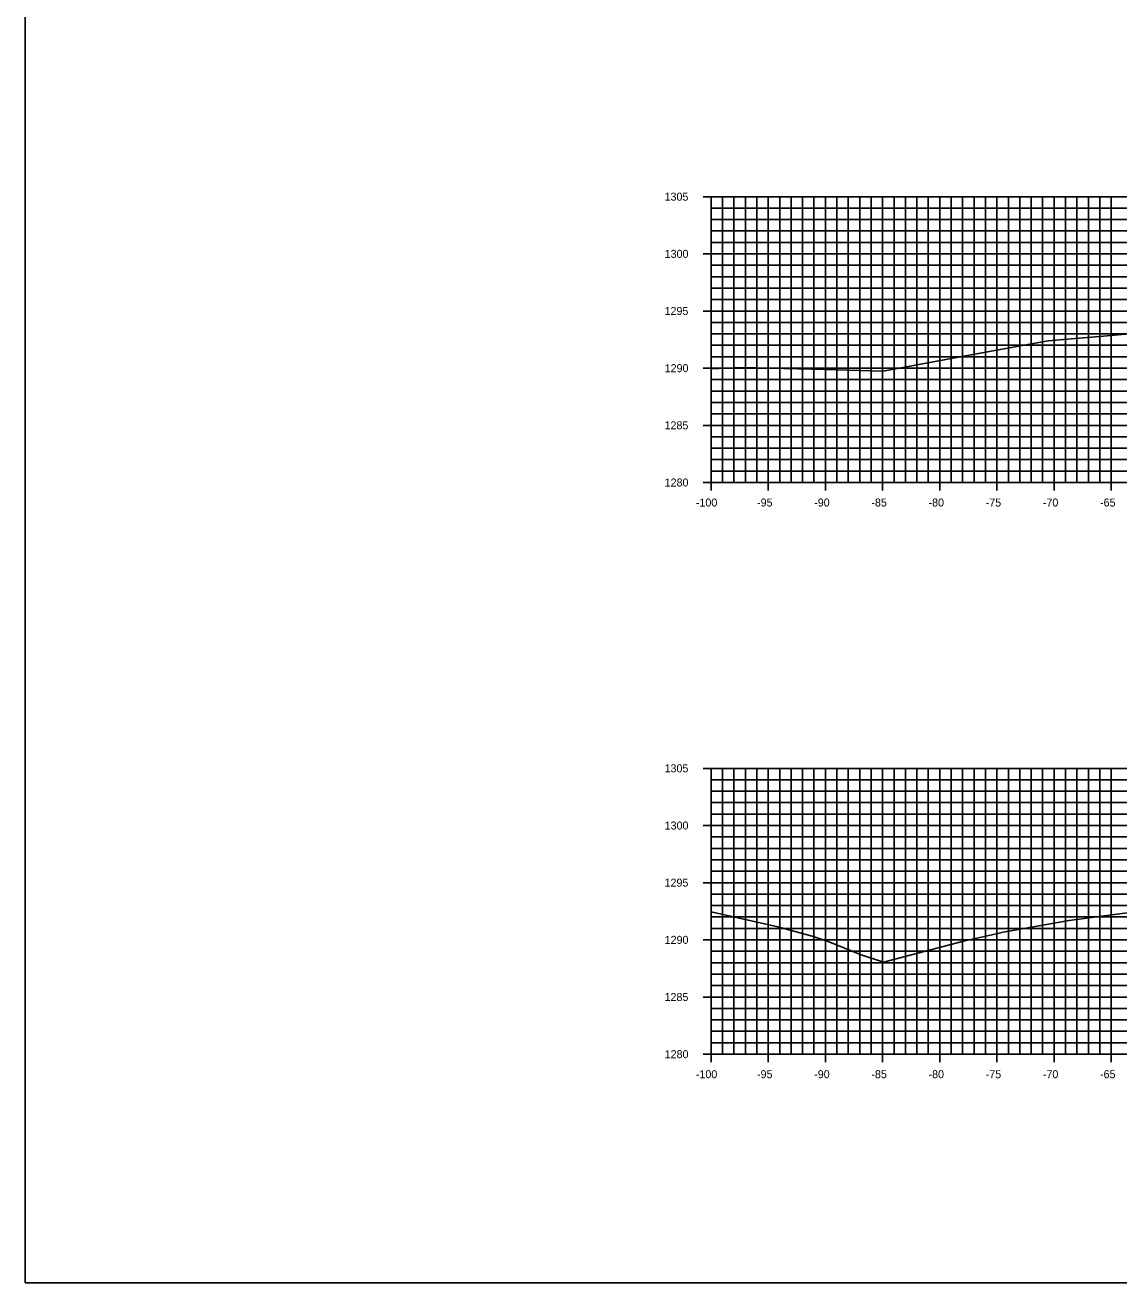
# Model space of a CAD drawing. Extents: x 674939 to 678919, y 750652 to 765176.
# Drawn here: x 678578.5 to 678674.2, y 757822.6 to 757932.6 of the extents above; entities that cross this region are included whole.
import ezdxf

# ---------------------------------------------------------------- set-up
doc = ezdxf.new("R2010")
doc.units = 0
for name, color, linetype in [('Level 10', 7, 'Continuous'), ('Level 20', 7, 'Continuous'), ('Level 4', 7, 'Continuous'), ('Level 8', 7, 'Continuous'), ('Level 9', 7, 'Continuous')]:
    doc.layers.add(name, color=color, linetype=linetype)

msp = doc.modelspace()

# ---------------------------------------------------------------- linework, layer by layer
at = {"layer": 'Level 10'}
for points in [[(678638.53, 757902.5), (678641.26, 757902.6), (678648.54, 757902.43), (678653.57, 757902.28), (678660.77, 757903.63), (678668.02, 757904.93), (678670.37, 757905.14), (678672.84, 757905.36), (678674.77, 757905.53)], [(678638.53, 757855), (678644.38, 757853.68), (678647.36, 757852.86), (678648.76, 757852.4), (678651.66, 757851.25), (678653.6, 757850.59), (678660.72, 757852.47), (678663.62, 757853.1), (678664.09, 757853.21), (678669.84, 757854.24), (678672.91, 757854.66), (678674.95, 757854.91)]]:
    msp.add_lwpolyline(points, dxfattribs=at)
at = {"layer": 'Level 20'}
for p, q in [((678638.53, 757917.55), (678838.53, 757917.55)), ((678638.53, 757892.55), (678638.53, 757917.55)), ((678638.53, 757916.55), (678838.53, 757916.55)), ((678639.53, 757892.55), (678639.53, 757917.55)), ((678640.53, 757892.55), (678640.53, 757917.55)), ((678641.53, 757892.55), (678641.53, 757917.55)), ((678642.53, 757892.55), (678642.53, 757917.55)), ((678643.53, 757892.55), (678643.53, 757917.55)), ((678644.53, 757892.55), (678644.53, 757917.55)), ((678645.53, 757892.55), (678645.53, 757917.55)), ((678646.53, 757892.55), (678646.53, 757917.55)), ((678647.53, 757892.55), (678647.53, 757917.55)), ((678648.53, 757892.55), (678648.53, 757917.55)), ((678649.53, 757892.55), (678649.53, 757917.55)), ((678650.53, 757892.55), (678650.53, 757917.55)), ((678651.53, 757892.55), (678651.53, 757917.55)), ((678652.53, 757892.55), (678652.53, 757917.55)), ((678653.53, 757892.55), (678653.53, 757917.55)), ((678654.53, 757892.55), (678654.53, 757917.55)), ((678655.53, 757892.55), (678655.53, 757917.55)), ((678656.53, 757892.55), (678656.53, 757917.55)), ((678657.53, 757892.55), (678657.53, 757917.55)), ((678658.53, 757892.55), (678658.53, 757917.55)), ((678659.53, 757892.55), (678659.53, 757917.55)), ((678660.53, 757892.55), (678660.53, 757917.55)), ((678661.53, 757892.55), (678661.53, 757917.55)), ((678662.53, 757892.55), (678662.53, 757917.55)), ((678663.53, 757892.55), (678663.53, 757917.55)), ((678664.53, 757892.55), (678664.53, 757917.55)), ((678665.53, 757892.55), (678665.53, 757917.55)), ((678666.53, 757892.55), (678666.53, 757917.55)), ((678667.53, 757892.55), (678667.53, 757917.55)), ((678668.53, 757892.55), (678668.53, 757917.55)), ((678669.53, 757892.55), (678669.53, 757917.55)), ((678670.53, 757892.55), (678670.53, 757917.55)), ((678671.53, 757892.55), (678671.53, 757917.55)), ((678672.53, 757892.55), (678672.53, 757917.55)), ((678673.53, 757892.55), (678673.53, 757917.55)), ((678638.53, 757915.55), (678838.53, 757915.55)), ((678638.53, 757914.55), (678838.53, 757914.55)), ((678638.53, 757913.55), (678838.53, 757913.55)), ((678638.53, 757912.55), (678838.53, 757912.55)), ((678638.53, 757911.55), (678838.53, 757911.55)), ((678638.53, 757910.55), (678838.53, 757910.55)), ((678638.53, 757909.55), (678838.53, 757909.55)), ((678638.53, 757908.55), (678838.53, 757908.55)), ((678638.53, 757907.55), (678838.53, 757907.55)), ((678638.53, 757906.55), (678838.53, 757906.55)), ((678638.53, 757905.55), (678838.53, 757905.55)), ((678638.53, 757904.55), (678838.53, 757904.55)), ((678638.53, 757903.55), (678838.53, 757903.55)), ((678638.53, 757902.55), (678838.53, 757902.55)), ((678638.53, 757901.55), (678838.53, 757901.55)), ((678638.53, 757900.55), (678838.53, 757900.55)), ((678638.53, 757899.55), (678838.53, 757899.55)), ((678638.53, 757898.55), (678838.53, 757898.55)), ((678638.53, 757897.55), (678838.53, 757897.55)), ((678638.53, 757896.55), (678838.53, 757896.55)), ((678638.53, 757895.55), (678838.53, 757895.55)), ((678638.53, 757894.55), (678838.53, 757894.55)), ((678638.53, 757893.55), (678838.53, 757893.55)), ((678638.53, 757892.55), (678838.53, 757892.55)), ((678638.53, 757867.55), (678838.53, 757867.55)), ((678638.53, 757842.55), (678638.53, 757867.55)), ((678639.53, 757842.55), (678639.53, 757867.55)), ((678640.53, 757842.55), (678640.53, 757867.55)), ((678641.53, 757842.55), (678641.53, 757867.55)), ((678642.53, 757842.55), (678642.53, 757867.55)), ((678643.53, 757842.55), (678643.53, 757867.55)), ((678644.53, 757842.55), (678644.53, 757867.55)), ((678645.53, 757842.55), (678645.53, 757867.55)), ((678646.53, 757842.55), (678646.53, 757867.55)), ((678647.53, 757842.55), (678647.53, 757867.55)), ((678648.53, 757842.55), (678648.53, 757867.55)), ((678649.53, 757842.55), (678649.53, 757867.55)), ((678650.53, 757842.55), (678650.53, 757867.55)), ((678651.53, 757842.55), (678651.53, 757867.55)), ((678652.53, 757842.55), (678652.53, 757867.55)), ((678653.53, 757842.55), (678653.53, 757867.55)), ((678654.53, 757842.55), (678654.53, 757867.55)), ((678655.53, 757842.55), (678655.53, 757867.55)), ((678656.53, 757842.55), (678656.53, 757867.55)), ((678657.53, 757842.55), (678657.53, 757867.55)), ((678658.53, 757842.55), (678658.53, 757867.55)), ((678659.53, 757842.55), (678659.53, 757867.55)), ((678660.53, 757842.55), (678660.53, 757867.55)), ((678661.53, 757842.55), (678661.53, 757867.55)), ((678662.53, 757842.55), (678662.53, 757867.55)), ((678663.53, 757842.55), (678663.53, 757867.55)), ((678664.53, 757842.55), (678664.53, 757867.55)), ((678665.53, 757842.55), (678665.53, 757867.55)), ((678666.53, 757842.55), (678666.53, 757867.55)), ((678667.53, 757842.55), (678667.53, 757867.55)), ((678668.53, 757842.55), (678668.53, 757867.55)), ((678669.53, 757842.55), (678669.53, 757867.55)), ((678670.53, 757842.55), (678670.53, 757867.55)), ((678671.53, 757842.55), (678671.53, 757867.55)), ((678672.53, 757842.55), (678672.53, 757867.55)), ((678673.53, 757842.55), (678673.53, 757867.55)), ((678638.53, 757866.55), (678838.53, 757866.55)), ((678638.53, 757865.55), (678838.53, 757865.55)), ((678638.53, 757864.55), (678838.53, 757864.55)), ((678638.53, 757863.55), (678838.53, 757863.55)), ((678638.53, 757862.55), (678838.53, 757862.55)), ((678638.53, 757861.55), (678838.53, 757861.55)), ((678638.53, 757860.55), (678838.53, 757860.55)), ((678638.53, 757859.55), (678838.53, 757859.55)), ((678638.53, 757858.55), (678838.53, 757858.55)), ((678638.53, 757857.55), (678838.53, 757857.55)), ((678638.53, 757856.55), (678838.53, 757856.55)), ((678638.53, 757855.55), (678838.53, 757855.55)), ((678638.53, 757854.55), (678838.53, 757854.55)), ((678638.53, 757853.55), (678838.53, 757853.55)), ((678638.53, 757852.55), (678838.53, 757852.55)), ((678638.53, 757851.55), (678838.53, 757851.55)), ((678638.53, 757850.55), (678838.53, 757850.55)), ((678638.53, 757849.55), (678838.53, 757849.55)), ((678638.53, 757848.55), (678838.53, 757848.55)), ((678638.53, 757847.55), (678838.53, 757847.55)), ((678638.53, 757846.55), (678838.53, 757846.55)), ((678638.53, 757845.55), (678838.53, 757845.55)), ((678638.53, 757844.55), (678838.53, 757844.55)), ((678638.53, 757843.55), (678838.53, 757843.55)), ((678638.53, 757842.55), (678838.53, 757842.55))]:
    msp.add_line(p, q, dxfattribs=at)
at = {"layer": 'Level 4'}
msp.add_lwpolyline([(678578.53, 757822.55), (678918.53, 757822.55), (678918.53, 758042.55), (678578.53, 758042.55)], close=True, dxfattribs=at)
at = {"layer": 'Level 8'}
for p, q in [((678637.83, 757917.55), (678639.23, 757917.55)), ((678638.53, 757892.55), (678638.53, 757917.55)), ((678638.53, 757916.55), (678638.88, 757916.55)), ((678638.53, 757915.55), (678638.88, 757915.55)), ((678638.53, 757914.55), (678638.88, 757914.55)), ((678638.53, 757913.55), (678638.88, 757913.55)), ((678637.83, 757912.55), (678639.23, 757912.55)), ((678638.53, 757911.55), (678638.88, 757911.55)), ((678638.53, 757910.55), (678638.88, 757910.55)), ((678638.53, 757909.55), (678638.88, 757909.55)), ((678638.53, 757908.55), (678638.88, 757908.55)), ((678637.83, 757907.55), (678639.23, 757907.55)), ((678638.53, 757906.55), (678638.88, 757906.55)), ((678638.53, 757905.55), (678638.88, 757905.55)), ((678638.53, 757904.55), (678638.88, 757904.55)), ((678638.53, 757903.55), (678638.88, 757903.55)), ((678637.83, 757902.55), (678639.23, 757902.55)), ((678638.53, 757901.55), (678638.88, 757901.55)), ((678638.53, 757900.55), (678638.88, 757900.55)), ((678638.53, 757899.55), (678638.88, 757899.55)), ((678638.53, 757898.55), (678638.88, 757898.55)), ((678637.83, 757897.55), (678639.23, 757897.55)), ((678638.53, 757896.55), (678638.88, 757896.55)), ((678638.53, 757895.55), (678638.88, 757895.55)), ((678638.53, 757894.55), (678638.88, 757894.55)), ((678638.53, 757893.55), (678638.88, 757893.55)), ((678637.83, 757892.55), (678639.23, 757892.55)), ((678638.53, 757891.85), (678638.53, 757893.25)), ((678638.53, 757892.55), (678838.53, 757892.55)), ((678643.53, 757891.85), (678643.53, 757893.25)), ((678648.53, 757891.85), (678648.53, 757893.25)), ((678653.53, 757891.85), (678653.53, 757893.25)), ((678658.53, 757891.85), (678658.53, 757893.25)), ((678663.53, 757891.85), (678663.53, 757893.25)), ((678668.53, 757891.85), (678668.53, 757893.25)), ((678673.53, 757891.85), (678673.53, 757893.25)), ((678637.83, 757867.55), (678639.23, 757867.55)), ((678638.53, 757842.55), (678638.53, 757867.55)), ((678638.53, 757866.55), (678638.88, 757866.55)), ((678638.53, 757865.55), (678638.88, 757865.55)), ((678638.53, 757864.55), (678638.88, 757864.55)), ((678638.53, 757863.55), (678638.88, 757863.55)), ((678637.83, 757862.55), (678639.23, 757862.55)), ((678638.53, 757861.55), (678638.88, 757861.55)), ((678638.53, 757860.55), (678638.88, 757860.55)), ((678638.53, 757859.55), (678638.88, 757859.55)), ((678638.53, 757858.55), (678638.88, 757858.55)), ((678637.83, 757857.55), (678639.23, 757857.55)), ((678638.53, 757856.55), (678638.88, 757856.55)), ((678638.53, 757855.55), (678638.88, 757855.55)), ((678638.53, 757854.55), (678638.88, 757854.55)), ((678638.53, 757853.55), (678638.88, 757853.55)), ((678637.83, 757852.55), (678639.23, 757852.55)), ((678638.53, 757851.55), (678638.88, 757851.55)), ((678638.53, 757850.55), (678638.88, 757850.55)), ((678638.53, 757849.55), (678638.88, 757849.55)), ((678638.53, 757848.55), (678638.88, 757848.55)), ((678637.83, 757847.55), (678639.23, 757847.55)), ((678638.53, 757846.55), (678638.88, 757846.55)), ((678638.53, 757845.55), (678638.88, 757845.55)), ((678638.53, 757844.55), (678638.88, 757844.55)), ((678638.53, 757843.55), (678638.88, 757843.55)), ((678638.53, 757841.85), (678638.53, 757843.25)), ((678643.53, 757841.85), (678643.53, 757843.25)), ((678648.53, 757841.85), (678648.53, 757843.25)), ((678653.53, 757841.85), (678653.53, 757843.25)), ((678658.53, 757841.85), (678658.53, 757843.25)), ((678663.53, 757841.85), (678663.53, 757843.25)), ((678668.53, 757841.85), (678668.53, 757843.25)), ((678673.53, 757841.85), (678673.53, 757843.25)), ((678637.83, 757842.55), (678639.23, 757842.55)), ((678638.53, 757842.55), (678838.53, 757842.55))]:
    msp.add_line(p, q, dxfattribs=at)

# ---------------------------------------------------------------- texts
at = {"layer": 'Level 9'}
for s, p in [('1305', (678634.46, 757917.2)), ('1300', (678634.47, 757912.2)), ('1295', (678634.46, 757907.2)), ('1290', (678634.47, 757902.2)), ('1285', (678634.46, 757897.2)), ('1280', (678634.47, 757892.2)), ('-100', (678637.2, 757890.45)), ('-95', (678642.55, 757890.45)), ('-90', (678647.55, 757890.45)), ('-85', (678652.55, 757890.45)), ('-80', (678657.55, 757890.45)), ('-75', (678662.55, 757890.45)), ('-70', (678667.55, 757890.45)), ('-65', (678672.55, 757890.45)), ('1305', (678634.46, 757867.2)), ('1300', (678634.47, 757862.2)), ('1295', (678634.46, 757857.2)), ('1290', (678634.47, 757852.2)), ('1285', (678634.46, 757847.2)), ('1280', (678634.47, 757842.2)), ('-100', (678637.2, 757840.45)), ('-95', (678642.55, 757840.45)), ('-90', (678647.55, 757840.45)), ('-85', (678652.55, 757840.45)), ('-80', (678657.55, 757840.45)), ('-75', (678662.55, 757840.45)), ('-70', (678667.55, 757840.45)), ('-65', (678672.55, 757840.45))]:
    msp.add_text(s, height=0.7, dxfattribs=at).set_placement(p)

doc.saveas('drawing.dxf')
